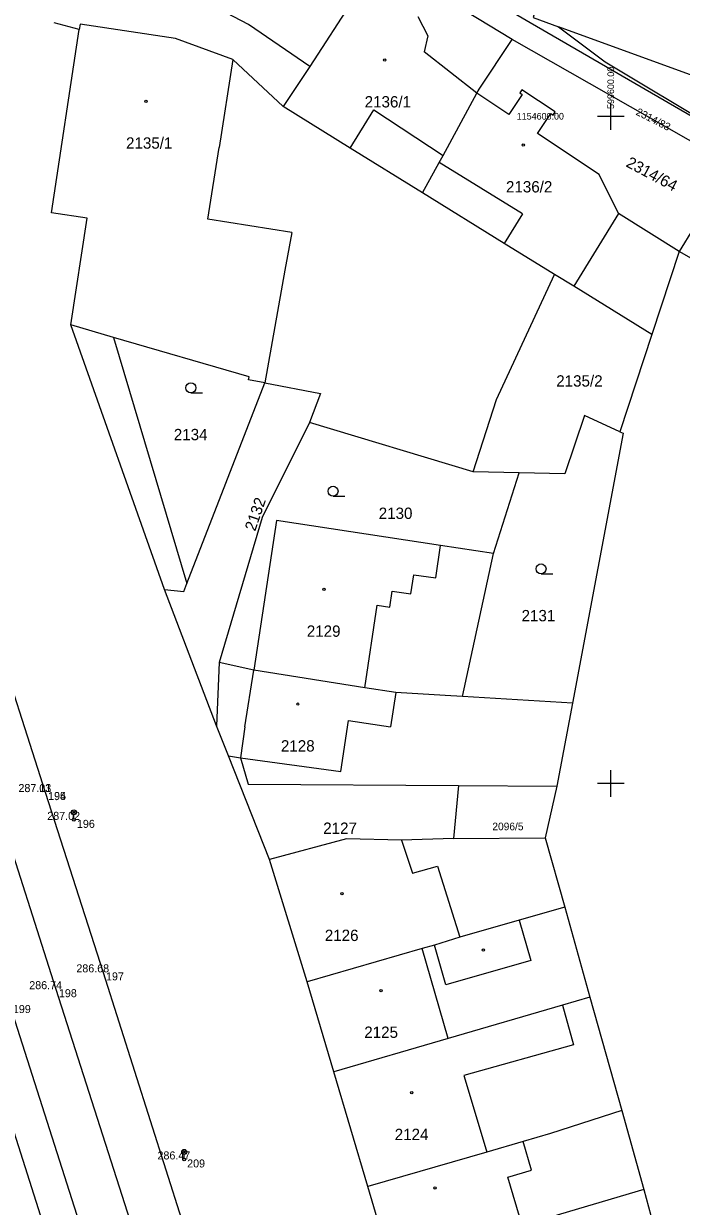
# Model space of a CAD drawing. Extents: x -599970 to -599524, y -1154772 to -1154457.
# Drawn here: x -599644 to -599594.7, y -1154681.7 to -1154593 of the extents above; entities that cross this region are included whole.
import ezdxf

# ---------------------------------------------------------------- set-up
doc = ezdxf.new("R2010")
doc.units = 0
for name, color, linetype in [('Z-ELEKTRICKE SKRINE LAMPY', 7, 'Continuous'), ('Z-KATASTRALNI MAPA', 7, 'Continuous'), ('Z-KRIZKY CTVERCOVE SITE', 7, 'Continuous'), ('Z-PODROBNE BODY', 7, 'Continuous'), ('Z-PODROBNE BODY-CISLO', 7, 'Continuous'), ('Z-PODROBNE BODY-VYSKA', 7, 'Continuous'), ('Z-POPIS KRIZKU CTVERCOVE SITE', 7, 'Continuous'), ('Z-VODOROVNE ZNACENI', 7, 'Continuous'), ('Z-ZPEVNENE PLOCHY', 7, 'Continuous')]:
    doc.layers.add(name, color=color, linetype=linetype)

msp = doc.modelspace()

# ---------------------------------------------------------------- linework, layer by layer
at = {"layer": 'Z-ELEKTRICKE SKRINE LAMPY'}
for p, q in [((-599640.362, -1154652.289), (-599640.098, -1154652.025)), ((-599640.094, -1154652.288), (-599640.358, -1154652.023)), ((-599640.23, -1154652.62), (-599640.23, -1154652.345)), ((-599632.102, -1154677.739), (-599631.838, -1154677.475)), ((-599631.834, -1154677.738), (-599632.098, -1154677.473)), ((-599631.97, -1154678.07), (-599631.97, -1154677.795))]:
    msp.add_line(p, q, dxfattribs=at)
for centre, radius in [((-599640.23, -1154652.157), 0.188), ((-599640.23, -1154652.72), 0.1), ((-599631.97, -1154677.607), 0.188), ((-599631.97, -1154678.17), 0.1)]:
    msp.add_circle(centre, radius, dxfattribs=at)
at = {"layer": 'Z-KATASTRALNI MAPA'}
for p, q in [((-599607.38, -1154594.23), (-599617.65, -1154588)), ((-599627.16, -1154593.12), (-599635.28, -1154588.82)), ((-599614.46, -1154592.51), (-599613.7, -1154593.96)), ((-599639.83, -1154593.48), (-599641.71, -1154593)), ((-599639.77, -1154593.08), (-599639.83, -1154593.48)), ((-599622.56, -1154596.26), (-599627.16, -1154593.12)), ((-599581.98, -1154601.27), (-599603.91, -1154593.29)), ((-599613.7, -1154593.96), (-599613.98, -1154595.16)), ((-599609.86, -1154597.96), (-599607.38, -1154594.23)), ((-599590.89, -1154603.63), (-599607.38, -1154594.23)), ((-599610.03, -1154598.27), (-599613.98, -1154595.16)), ((-599628.32, -1154595.73), (-599629.35, -1154602.32)), ((-599610.03, -1154598.27), (-599609.86, -1154597.96)), ((-599619.53, -1154602.38), (-599624.56, -1154599.26)), ((-599619.53, -1154602.38), (-599617.76, -1154599.51)), ((-599617.76, -1154599.51), (-599612.57, -1154602.92)), ((-599630.21, -1154607.69), (-599629.35, -1154602.32)), ((-599614.1, -1154605.74), (-599619.53, -1154602.38)), ((-599606.61, -1154607.31), (-599612.85, -1154603.45)), ((-599590.89, -1154603.63), (-599594.88, -1154610.13)), ((-599623.91, -1154608.7), (-599630.21, -1154607.69)), ((-599606.61, -1154607.31), (-599607.98, -1154609.52)), ((-599599.42, -1154607.29), (-599602.78, -1154612.73)), ((-599623.91, -1154608.7), (-599624.42, -1154611.53)), ((-599594.88, -1154610.13), (-599596.92, -1154616.35)), ((-599576.64, -1154620.46), (-599594.88, -1154610.13)), ((-599624.42, -1154611.53), (-599625.93, -1154619.97)), ((-599637.27, -1154616.56), (-599640.47, -1154615.63)), ((-599596.92, -1154616.35), (-599599.31, -1154623.65)), ((-599631.76, -1154635.01), (-599625.93, -1154619.97)), ((-599631.466, -1154620.72), (-599630.591, -1154620.72)), ((-599610.32, -1154626.64), (-599622.57, -1154622.95)), ((-599599.08, -1154623.73), (-599602.88, -1154643.98)), ((-599599.31, -1154623.65), (-599599.08, -1154623.73)), ((-599606.87, -1154626.72), (-599610.32, -1154626.64)), ((-599608.78, -1154632.76), (-599606.87, -1154626.72)), ((-599620.816, -1154628.47), (-599619.941, -1154628.47)), ((-599613.12, -1154634.59), (-599612.76, -1154632.15)), ((-599608.78, -1154632.76), (-599612.76, -1154632.15)), ((-599611.12, -1154643.48), (-599608.78, -1154632.76)), ((-599614.98, -1154635.79), (-599614.77, -1154634.35)), ((-599614.77, -1154634.35), (-599613.12, -1154634.59)), ((-599605.226, -1154634.29), (-599604.351, -1154634.29)), ((-599633.45, -1154635.46), (-599631.99, -1154635.6)), ((-599629.56, -1154645.67), (-599633.45, -1154635.46)), ((-599631.99, -1154635.6), (-599631.76, -1154635.01)), ((-599616.56, -1154636.78), (-599616.38, -1154635.58)), ((-599616.38, -1154635.58), (-599614.98, -1154635.79)), ((-599618.43, -1154642.83), (-599617.5, -1154636.64)), ((-599617.5, -1154636.64), (-599616.56, -1154636.78)), ((-599629.36, -1154640.93), (-599629.56, -1154645.67)), ((-599626.74, -1154641.5), (-599629.36, -1154640.93)), ((-599627.42, -1154645.76), (-599626.74, -1154641.5)), ((-599616.12, -1154643.18), (-599616.5, -1154645.75)), ((-599602.88, -1154643.98), (-599611.12, -1154643.48)), ((-599602.88, -1154643.98), (-599604.05, -1154650.2)), ((-599620.24, -1154649.1), (-599619.65, -1154645.27)), ((-599619.65, -1154645.27), (-599616.5, -1154645.75)), ((-599628.66, -1154647.93), (-599629.56, -1154645.67)), ((-599627.42, -1154645.76), (-599627.74, -1154648.06)), ((-599625.58, -1154655.7), (-599628.66, -1154647.93)), ((-599627.74, -1154648.06), (-599620.24, -1154649.1)), ((-599611.4, -1154650.15), (-599611.78, -1154654.12)), ((-599611.4, -1154650.15), (-599604.05, -1154650.2)), ((-599604.05, -1154650.2), (-599604.92, -1154654.06)), ((-599611.78, -1154654.12), (-599604.92, -1154654.06)), ((-599604.92, -1154654.06), (-599603.44, -1154659.26)), ((-599615.68, -1154654.24), (-599614.87, -1154656.72)), ((-599622.76, -1154664.85), (-599625.58, -1154655.7)), ((-599614.87, -1154656.72), (-599612.99, -1154656.18)), ((-599612.99, -1154656.18), (-599611.3, -1154661.51)), ((-599603.44, -1154659.26), (-599601.56, -1154666.01)), ((-599606.87, -1154660.24), (-599606, -1154663.25)), ((-599611.3, -1154661.51), (-599613.22, -1154662.1)), ((-599612.36, -1154665.08), (-599613.22, -1154662.1)), ((-599612.19, -1154669.11), (-599614.13, -1154662.36)), ((-599606, -1154663.25), (-599612.36, -1154665.08)), ((-599620.75, -1154671.61), (-599622.76, -1154664.85)), ((-599601.56, -1154666.01), (-599599.16, -1154674.51)), ((-599603.62, -1154666.61), (-599602.79, -1154669.57)), ((-599602.79, -1154669.57), (-599611.01, -1154671.88)), ((-599618.2, -1154680.21), (-599620.75, -1154671.61)), ((-599611.01, -1154671.88), (-599609.87, -1154675.71)), ((-599599.16, -1154674.51), (-599604.51, -1154676.22)), ((-599599.16, -1154674.51), (-599597.53, -1154680.43)), ((-599609.87, -1154675.71), (-599609.3, -1154677.62)), ((-599605.93, -1154678.98), (-599606.56, -1154676.82)), ((-599607.71, -1154679.5), (-599605.93, -1154678.98)), ((-599606.65, -1154683.13), (-599607.71, -1154679.5)), ((-599616.47, -1154686.03), (-599618.2, -1154680.21)), ((-599597.53, -1154680.43), (-599605.12, -1154682.67)), ((-599597.53, -1154680.43), (-599595.94, -1154686.2))]:
    msp.add_line(p, q, dxfattribs=at)
for points in [[(-599583.46, -1154606.09), (-599606.05, -1154592.99), (-599616.82, -1154586.68), (-599619.77, -1154584.89)], [(-599619.28, -1154591.18), (-599622.56, -1154596.26), (-599624.56, -1154599.26)], [(-599605.64, -1154591.99), (-599605.82, -1154592.59), (-599603.91, -1154593.29)], [(-599633.45, -1154635.46), (-599640.47, -1154615.63), (-599639.24, -1154607.62), (-599641.91, -1154607.22), (-599639.83, -1154593.48)], [(-599624.56, -1154599.26), (-599628.32, -1154595.73), (-599632.63, -1154594.16), (-599639.77, -1154593.08)], [(-599603.91, -1154593.29), (-599600.41, -1154595.91), (-599583.46, -1154606.09)], [(-599614.1, -1154605.74), (-599612.85, -1154603.45), (-599612.57, -1154602.92), (-599610.03, -1154598.27)], [(-599594.88, -1154610.13), (-599599.42, -1154607.29), (-599600.87, -1154604.35), (-599605.5, -1154601.28), (-599604.5, -1154599.78), (-599604.32, -1154599.9), (-599604.16, -1154599.67), (-599606.67, -1154598), (-599606.82, -1154598.24), (-599606.64, -1154598.36), (-599607.64, -1154599.86), (-599610.03, -1154598.27)], [(-599604.21, -1154611.85), (-599607.98, -1154609.52), (-599614.1, -1154605.74)], [(-599610.32, -1154626.64), (-599608.56, -1154621.21), (-599604.21, -1154611.85)], [(-599596.92, -1154616.35), (-599602.78, -1154612.73), (-599604.21, -1154611.85)], [(-599627.1, -1154619.52), (-599637.27, -1154616.56), (-599631.76, -1154635.01)], [(-599625.93, -1154619.97), (-599627.14, -1154619.74), (-599627.1, -1154619.52)], [(-599625.93, -1154619.97), (-599621.76, -1154620.76), (-599622.57, -1154622.95)], [(-599622.57, -1154622.95), (-599626.12, -1154630.05), (-599629.36, -1154640.93)], [(-599599.31, -1154623.65), (-599601.98, -1154622.41), (-599603.44, -1154626.8), (-599606.87, -1154626.72)], [(-599612.76, -1154632.15), (-599625.04, -1154630.28), (-599626.74, -1154641.5)], [(-599616.12, -1154643.18), (-599618.43, -1154642.83), (-599626.74, -1154641.5)], [(-599611.12, -1154643.48), (-599612.42, -1154643.4), (-599616.12, -1154643.18)], [(-599628.66, -1154647.93), (-599627.74, -1154648.06), (-599627.18, -1154650.05), (-599611.4, -1154650.15)], [(-599611.78, -1154654.12), (-599615.68, -1154654.24), (-599619.81, -1154654.15), (-599625.58, -1154655.7)], [(-599603.44, -1154659.26), (-599606.87, -1154660.24), (-599611.3, -1154661.51)], [(-599613.22, -1154662.1), (-599614.13, -1154662.36), (-599622.76, -1154664.85)], [(-599601.56, -1154666.01), (-599603.62, -1154666.61), (-599612.19, -1154669.11), (-599620.75, -1154671.61)], [(-599604.51, -1154676.22), (-599606.56, -1154676.82), (-599609.3, -1154677.62), (-599618.2, -1154680.21)]]:
    msp.add_lwpolyline(points, dxfattribs=at)
for centre, radius in [((-599616.933, -1154595.78), 0.0875), ((-599634.843, -1154598.87), 0.0875), ((-599606.553, -1154602.15), 0.0875), ((-599631.466, -1154620.345), 0.375), ((-599620.816, -1154628.095), 0.375), ((-599605.226, -1154633.915), 0.375), ((-599621.503, -1154635.45), 0.0875), ((-599623.453, -1154644.05), 0.0875), ((-599620.153, -1154658.25), 0.0875), ((-599609.543, -1154662.48), 0.0875), ((-599617.213, -1154665.51), 0.0875), ((-599614.913, -1154673.17), 0.0875), ((-599613.163, -1154680.3), 0.0875)]:
    msp.add_circle(centre, radius, dxfattribs=at)
at = {"layer": 'Z-KRIZKY CTVERCOVE SITE'}
for p, q in [((-599600, -1154601), (-599600, -1154599)), ((-599599, -1154600), (-599601, -1154600)), ((-599600, -1154651), (-599600, -1154649)), ((-599599, -1154650), (-599601, -1154650))]:
    msp.add_line(p, q, dxfattribs=at)
at = {"layer": 'Z-PODROBNE BODY'}
for p, q in [((-599642.39, -1154650.63), (-599642.39, -1154650.63)), ((-599642.39, -1154650.64), (-599642.39, -1154650.64)), ((-599640.23, -1154652.72), (-599640.23, -1154652.72)), ((-599638.05, -1154664.15), (-599638.05, -1154664.15)), ((-599641.58, -1154665.41), (-599641.58, -1154665.41)), ((-599631.97, -1154678.17), (-599631.97, -1154678.17))]:
    msp.add_line(p, q, dxfattribs=at)
at = {"layer": 'Z-VODOROVNE ZNACENI'}
for points in [[(-599694.02, -1154499.99), (-599689.54, -1154514.32), (-599685.46, -1154527.42), (-599683.24, -1154534.53), (-599677.91, -1154551.43), (-599673.26, -1154566.04), (-599670.15, -1154575.91), (-599664.69, -1154593.08), (-599661.63, -1154602.65), (-599657.71, -1154615.01), (-599654.33, -1154625.58), (-599650.3, -1154638.13), (-599646.03, -1154651.51), (-599641.58, -1154665.41), (-599629.85, -1154702.06), (-599625.38, -1154716.06)], [(-599697.63, -1154501.15), (-599693.46, -1154514.34), (-599689.12, -1154528.02), (-599685.9, -1154538.22), (-599681.17, -1154553.13), (-599676.65, -1154567.39), (-599673.59, -1154577), (-599671.31, -1154584.14), (-599668.11, -1154594.2), (-599666.34, -1154599.75), (-599661.15, -1154616.02), (-599657.79, -1154626.57), (-599653.82, -1154639.02), (-599649.52, -1154652.61), (-599645.03, -1154666.6), (-599639.28, -1154684.62), (-599637.35, -1154690.63), (-599633.4, -1154703.39)]]:
    msp.add_lwpolyline(points, dxfattribs=at)
at = {"layer": 'Z-ZPEVNENE PLOCHY'}
for points in [[(-599672.4, -1154589.48), (-599670.73, -1154594.81), (-599667.36, -1154605.26), (-599665.4, -1154611.41), (-599665.09, -1154612.38), (-599663.59, -1154616.97), (-599663.32, -1154617.94), (-599660.4, -1154627.02), (-599656.6, -1154638.85), (-599656.29, -1154639.8), (-599655.25, -1154643.15), (-599654.93, -1154644.12), (-599651.93, -1154653.5), (-599647.41, -1154667.76), (-599641.59, -1154686.01), (-599637.45, -1154690.75), (-599637.27, -1154691.05), (-599637.22, -1154691.51), (-599636.57, -1154701.7), (-599631.18, -1154718.34)], [(-599646.76, -1154636.94), (-599646.48, -1154637.9), (-599642.39, -1154650.64), (-599638.05, -1154664.15), (-599632.16, -1154682.64), (-599630.36, -1154688.43), (-599622.63, -1154699.78), (-599618.24, -1154713.84)]]:
    msp.add_lwpolyline(points, dxfattribs=at)

# ---------------------------------------------------------------- texts
at = {"layer": 'Z-KATASTRALNI MAPA'}
for s, height, p in [('2136/1', 0.85, (-599618.444, -1154599.33)), ('2135/1', 0.85, (-599636.327, -1154602.42)), ('2136/2', 0.85, (-599607.854, -1154605.7)), ('2135/2', 0.85, (-599604.088, -1154620.25)), ('2134', 0.85, (-599632.748, -1154624.27)), ('2130', 0.85, (-599617.391, -1154630.17)), ('2131', 0.85, (-599606.684, -1154637.84)), ('2129', 0.85, (-599622.781, -1154639)), ('2128', 0.85, (-599624.721, -1154647.6)), ('2127', 0.85, (-599621.551, -1154653.77)), ('2096/5', 0.57, (-599608.872, -1154653.5)), ('2126', 0.85, (-599621.431, -1154661.8)), ('2125', 0.85, (-599618.475, -1154669.06)), ('2124', 0.85, (-599616.191, -1154676.72))]:
    msp.add_text(s, height=height, dxfattribs=at).set_placement(p)
for s, height, rotation, p in [('2314/83', 0.57, 333, (-599598.166, -1154599.849)), ('2314/64', 0.85, 332, (-599598.922, -1154603.724)), ('2132', 0.85, 71, (-599626.652, -1154631.136))]:
    msp.add_text(s, height=height, rotation=rotation, dxfattribs=at).set_placement(p)
at = {"layer": 'Z-PODROBNE BODY-CISLO'}
for s, p in [(' 195', (-599642.39, -1154651.23)), (' 194', (-599642.39, -1154651.24)), (' 196', (-599640.23, -1154653.32)), (' 197', (-599638.05, -1154664.75)), (' 198', (-599641.58, -1154666.01)), (' 199', (-599645.03, -1154667.2)), (' 209', (-599631.97, -1154678.77))]:
    msp.add_text(s, height=0.6, dxfattribs=at).set_placement(p)
at = {"layer": 'Z-PODROBNE BODY-VYSKA'}
for s, p in [('287.13 ', (-599644.39, -1154650.63)), ('287.01 ', (-599644.39, -1154650.64)), ('287.02 ', (-599642.23, -1154652.72)), ('286.68 ', (-599640.05, -1154664.15)), ('286.74 ', (-599643.58, -1154665.41)), ('286.47 ', (-599633.97, -1154678.17))]:
    msp.add_text(s, height=0.6, dxfattribs=at).set_placement(p)
at = {"layer": 'Z-POPIS KRIZKU CTVERCOVE SITE'}
msp.add_text('   599600.00', height=0.5, rotation=90, dxfattribs=at).set_placement((-599599.75, -1154600))
msp.add_text('   1154600.00', height=0.5, dxfattribs=at).set_placement((-599607.6, -1154600.24))

doc.saveas('drawing.dxf')
